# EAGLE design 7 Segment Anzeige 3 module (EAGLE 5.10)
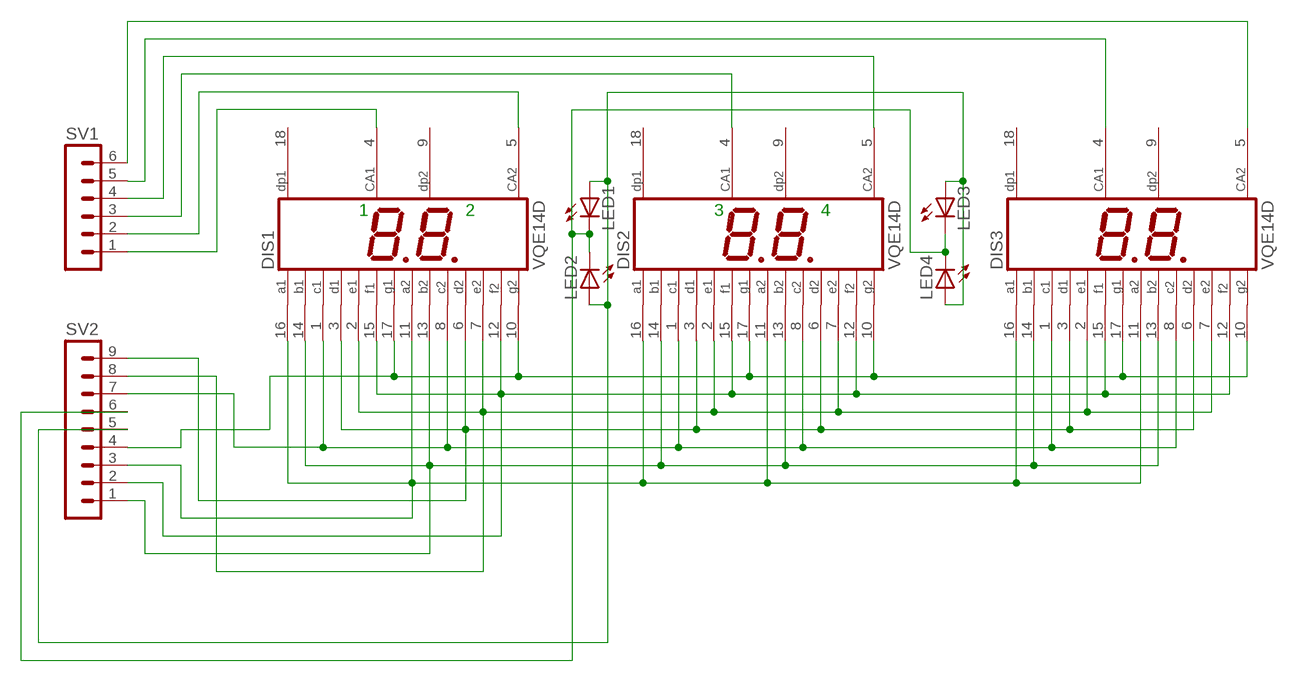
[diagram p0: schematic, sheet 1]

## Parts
DIS1  VQE14D  [HDSP-R]
DIS2  VQE14D  [HDSP-R]
DIS3  VQE14D  [HDSP-R]
LED1  LED3MM  [LED3MM]
LED2  LED3MM  [LED3MM]
LED3  LED3MM  [LED3MM]
LED4  LED3MM  [LED3MM]
SV1  MA06-1  [MA06-1]
SV2  MA09-1  [MA09-1]

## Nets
N$1: DIS1.10(G2) DIS1.17(G1) DIS2.10(G2) DIS2.17(G1) DIS3.10(G2) DIS3.17(G1) SV2.4
N$2: DIS1.12(F2) DIS1.15(F1) DIS2.12(F2) DIS2.15(F1) DIS3.12(F2) DIS3.15(F1) SV2.2
N$3: DIS1.2(E1) DIS1.7(E2) DIS2.2(E1) DIS2.7(E2) DIS3.2(E1) DIS3.7(E2) SV2.8
N$4: DIS1.3(D1) DIS1.6(D2) DIS2.3(D1) DIS2.6(D2) DIS3.3(D1) DIS3.6(D2) SV2.9
N$5: DIS1.1(C1) DIS1.8(C2) DIS2.1(C1) DIS2.8(C2) DIS3.1(C1) DIS3.8(C2) SV2.7
N$6: DIS1.13(B2) DIS1.14(B1) DIS2.13(B2) DIS2.14(B1) DIS3.13(B2) DIS3.14(B1) SV2.1
N$7: DIS1.11(A2) DIS1.16(A1) DIS2.11(A2) DIS2.16(A1) DIS3.11(A2) DIS3.16(A1) SV2.3
N$8: DIS3.4(CA1) SV1.5
N$9: DIS3.5(CA2) SV1.6
N$10: LED1.K(C) LED2.K(C) LED3.K(C) LED4.K(C) SV2.6
N$12: LED1.A LED2.A LED3.A LED4.A SV2.5
N$17: DIS1.4(CA1) SV1.1
N$18: DIS1.5(CA2) SV1.2
N$19: DIS2.4(CA1) SV1.3
N$20: DIS2.5(CA2) SV1.4
Unconnected: DIS1.9(DP2) DIS1.18(DP1) DIS2.9(DP2) DIS2.18(DP1) DIS3.9(DP2) DIS3.18(DP1)

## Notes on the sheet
- 1 | 2 | 3 | 4

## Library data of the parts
DIS1-DIS3 = LED_7_Segment_VQE14:VQE14D: LED DISPLAY 2 x 1 character 7 segment, decimal points right
LED1-LED4 = led:LED: LED
SV1 = con-lstb:MA06-1: PIN HEADER
SV2 = con-lstb:MA09-1: PIN HEADER

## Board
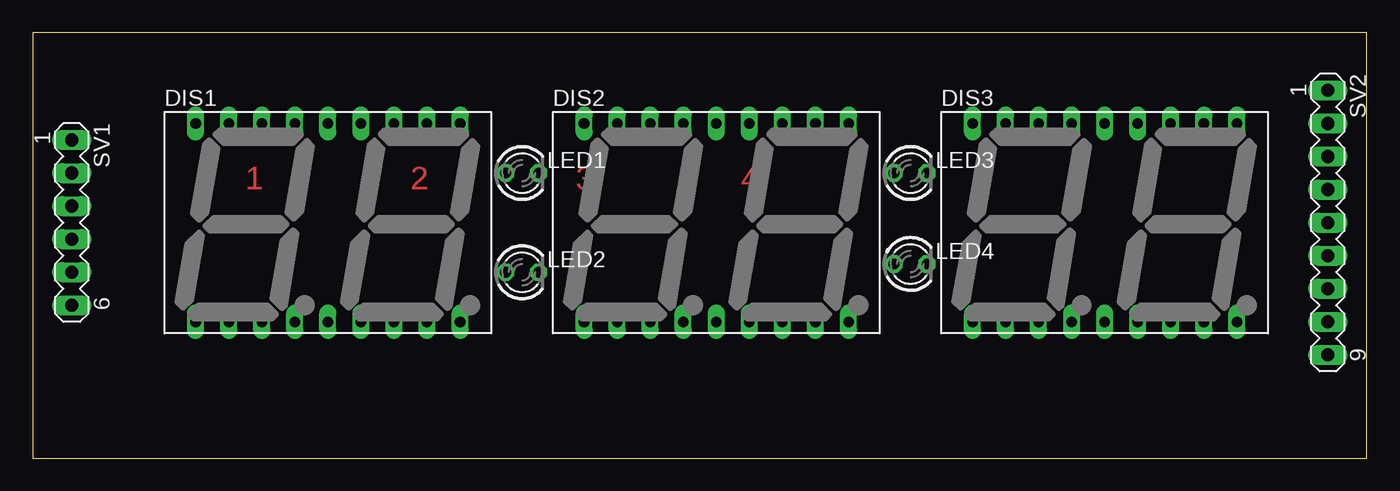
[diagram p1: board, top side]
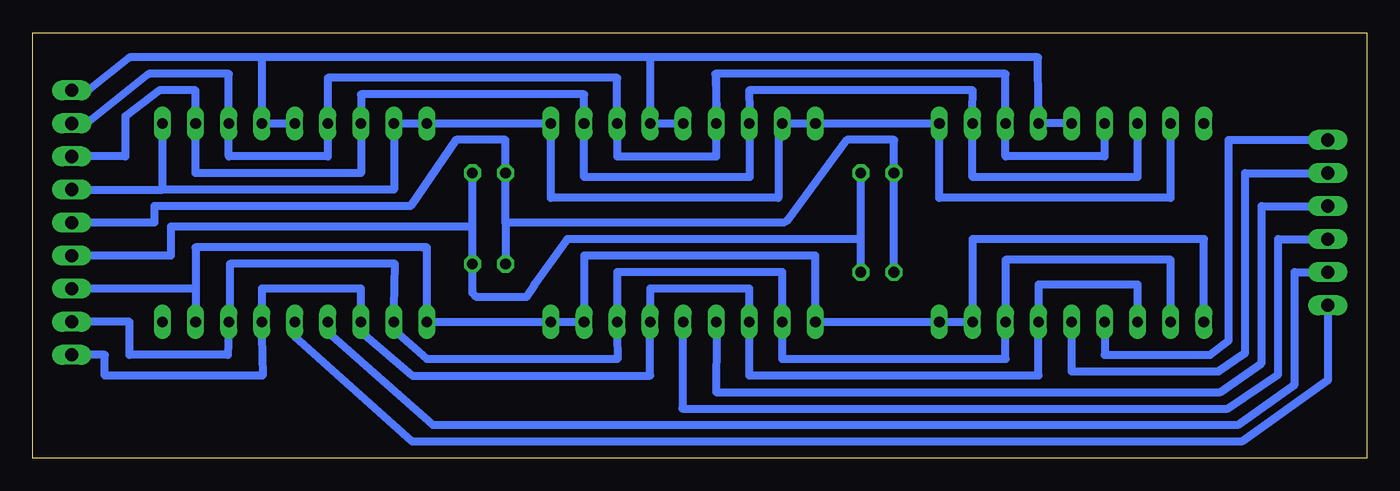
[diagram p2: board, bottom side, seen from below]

Size 102.54 x 32.69 mm. Coordinates in mm from the lower left corner, seen from the top.
Outline: 0,0 102.54,0 102.54,32.69 0,32.69 0,0
Copper layers 1*16: Top 0.035mm / dielectric 1.5mm / Bottom 0.035mm
Design rules: minimum track width 12mil, minimum drill 24mil, track to track 10mil, track to pad 10mil, pad to pad 8mil, via to via 8mil, smd to smd 8mil, copper to edge 40mil, drill to drill 8mil, minimum pad ring 10mil, minimum via ring 8mil, stop-mask expansion 4mil, vias tented up to drill 0mil, thermal gap 10mil

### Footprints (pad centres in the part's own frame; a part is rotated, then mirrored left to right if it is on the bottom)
HDSP-R = drill 0.813 long: 1 -10.16,-7.62; 2 -7.62,-7.62; 3 -5.08,-7.62; 4 -2.54,-7.62; 5 0,-7.62; 6 2.54,-7.62; 7 5.08,-7.62; 8 7.62,-7.62; 9 10.16,-7.62; 10 10.16,7.62; 11 7.62,7.62; 12 5.08,7.62; 13 2.54,7.62; 14 0,7.62; 15 -2.54,7.62; 16 -5.08,7.62; 17 -7.62,7.62; 18 -10.16,7.62
LED3MM = drill 0.813 octagon: A -1.27,0; K 1.27,0
MA06-1 = drill 1.016 long: 1 -6.35,0; 2 -3.81,0; 3 -1.27,0; 4 1.27,0; 5 3.81,0; 6 6.35,0
MA09-1 = drill 1.016 long: 1 -10.16,0; 2 -7.62,0; 3 -5.08,0; 4 -2.54,0; 5 0,0; 6 2.54,0; 7 5.08,0; 8 7.62,0; 9 10.16,0

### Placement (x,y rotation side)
DIS1  22.7,18.09 0 top
DIS2  52.54,18.09 0 top
DIS3  82.39,18.09 0 top
LED1  37.62,21.9 0 top
LED2  37.62,14.28 0 top
LED3  67.46,21.9 0 top
LED4  67.46,14.92 0 top
SV1  3.01,18.09 270 top
SV2  99.53,18.09 270 top

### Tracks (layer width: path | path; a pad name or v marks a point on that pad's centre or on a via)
N$1
  Bottom 0.61: DIS1.17 15.08,20 32.85,20 DIS1.10 DIS2.17 45.24,25.71 45.24,20 62.7,20 DIS2.10 DIS3.17 74.77,20.63 92.55,20.63 | SV2.4 92.55,20.63 | 92.55,20.63 DIS3.10
N$2
  Bottom 0.61: DIS1.15 20.16,23.17 27.78,23.17 DIS1.12 27.78,29.52 50,29.52 | 50.06,29.52 50.05,29.19 | 50.05,29.19 50,26.73 DIS2.15 | SV2.2 98.37,25.71 93.61,29.52 87.47,29.52 DIS3.12 87.47,23.17 79.84,23.17 DIS3.15 79.84,29.2 57.62,29.2 DIS2.12 57.62,23.17 50,23.17 DIS2.15 | 50,29.52 50.05,29.52 50.05,29.19 | DIS2.15 50,29.52
N$3
  Bottom 0.61: DIS1.2 15.08,15.23 27.78,15.23 27.78,11.11 DIS1.7 27.78,7.61 44.92,7.61 DIS2.2 44.92,14.28 57.62,14.28 DIS2.7 57.62,9.5 57.6,7.61 72.23,7.61 74.77,9.84 DIS3.2 74.77,11.5 74.69,14.92 87.37,14.92 87.37,10.47 DIS3.7 87.47,9.59 87.53,7.93 95.09,7.93 95.09,10.47 SV2.8
N$4
  Bottom 0.61: DIS1.3 17.62,13.33 25.23,13.33 DIS1.6 25.23,6.35 47.46,6.35 DIS2.3 47.46,13.01 55.08,13.01 DIS2.6 55.08,6.35 73.36,6.35 77.31,9.65 DIS3.3 77.31,13.01 84.92,13.01 DIS3.6 84.92,9.46 84.86,6.35 96.99,6.35 96.99,7.93 SV2.9
N$5
  Bottom 0.61: DIS1.1 12.54,16.82 30.32,16.82 DIS1.8 | DIS1.8 30.32,10.22 | 90.01,13.01 DIS3.8 | 90.01,13.01 90.01,16.19 72.54,16.19 72.23,16.19 DIS3.1 DIS2.8 60.16,15.55 42.38,15.55 DIS2.1 DIS1.8 | 90.01,13.01 SV2.7
N$6
  Bottom 0.61: DIS1.14 DIS1.13 25.23,26.94 25.27,30.79 55.08,30.79 | 55.08,30.79 84.92,30.79 | DIS2.14 DIS2.13 55.08,30.79 | 84.92,30.79 DIS3.13 DIS3.14 | 84.92,30.79 95.09,30.79 98.26,28.25 SV2.1
N$7
  Bottom 0.61: DIS1.16 17.62,21.59 30.32,21.59 DIS1.11 30.32,26.68 30.3,28.25 47.48,28.25 47.46,26.68 DIS2.16 47.46,24.74 47.44,21.59 60.16,21.59 DIS2.11 60.16,27.93 77.31,27.93 DIS3.16 77.31,21.9 90.01,21.9 DIS3.11 90.01,28.25 92.8,28.25 95.4,26.28 95.4,23.17 SV2.3
N$8
  Bottom 0.61: DIS3.4 79.84,9.66 71.76,2.54 9.93,2.54 5.55,5.65 5.55,14.28 SV1.5
N$9
  Bottom 0.61: SV1.6 3.01,5.99 9.63,1.26 73.36,1.26 82.39,9.34 DIS3.5
N$10
  Bottom 0.61: LED2.K 38.89,16.82 | 38.89,16.82 LED1.K | 68.73,17.77 LED4.K 68.73,12.7 68.42,12.38 64.61,12.38 63.97,13.33 61.43,16.82 38.89,16.82 | 68.73,17.77 LED3.K | SV2.6 91.91,15.55 91.91,17.77 68.73,17.77
N$12
  Bottom 0.61: LED2.A LED1.A 36.35,24.44 39.95,24.44 44.53,18.24 44.82,18.09 66.19,18.09 | 66.19,18.09 LED4.A | 66.19,18.09 LED3.A 66.19,24.44 70,24.44 73.5,19.36 93.18,19.36 93.18,18.09 SV2.5
N$17
  Bottom 0.61: DIS1.4 20.16,7.93 12.05,7.93 10.63,9.03 10.63,24.44 SV1.1
N$18
  Bottom 0.61: DIS1.5 22.7,6.66 11.42,6.66 9.36,8.08 9.36,21.9 SV1.2
N$19
  Bottom 0.61: DIS2.4 50,9.51 50.01,5.08 11.27,5.08 8.09,7.3 8.09,19.36 SV1.3
N$20
  Bottom 0.61: DIS2.5 52.6,10.47 52.6,3.81 10.73,3.81 6.82,6.44 6.82,16.82 SV1.4

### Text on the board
Top: 1 | 2 | 3 | 4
